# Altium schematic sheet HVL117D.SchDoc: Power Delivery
size 431 x 279 mm; Date: Not shown in title block; ApprovedBy: Not shown in title block; CheckedBy: Not shown in title block; Author: Not shown in title block; CompanyName: Not shown in title block; Engineer: Not shown in title block; Organization: Not shown in title block; Address1: Not shown in title block; Address2: Not shown in title block; Address3: Not shown in title block; Address4: Not shown in title block; DocumentNumber: 2; Revision: Use project parameter SCH_Rev; SheetNumber: 2; SheetTotal: 4; PageSetup: Record=PageOptions¦CenterHorizontal=True¦CenterVertical=True¦PrintScale=0.64¦XCorrection=1.00¦YCorrection=1.00¦PrintKind=0¦BorderSize=5000000¦LeftOffset=0¦BottomOffset=0¦Orientation=2¦PaperLength=1000¦PaperWidth=1000¦Scale=100¦PaperSource=15¦PrintQuality=600¦MediaType=1¦DitherType=10¦PaperKind=Letter¦PrintScaleMode=1
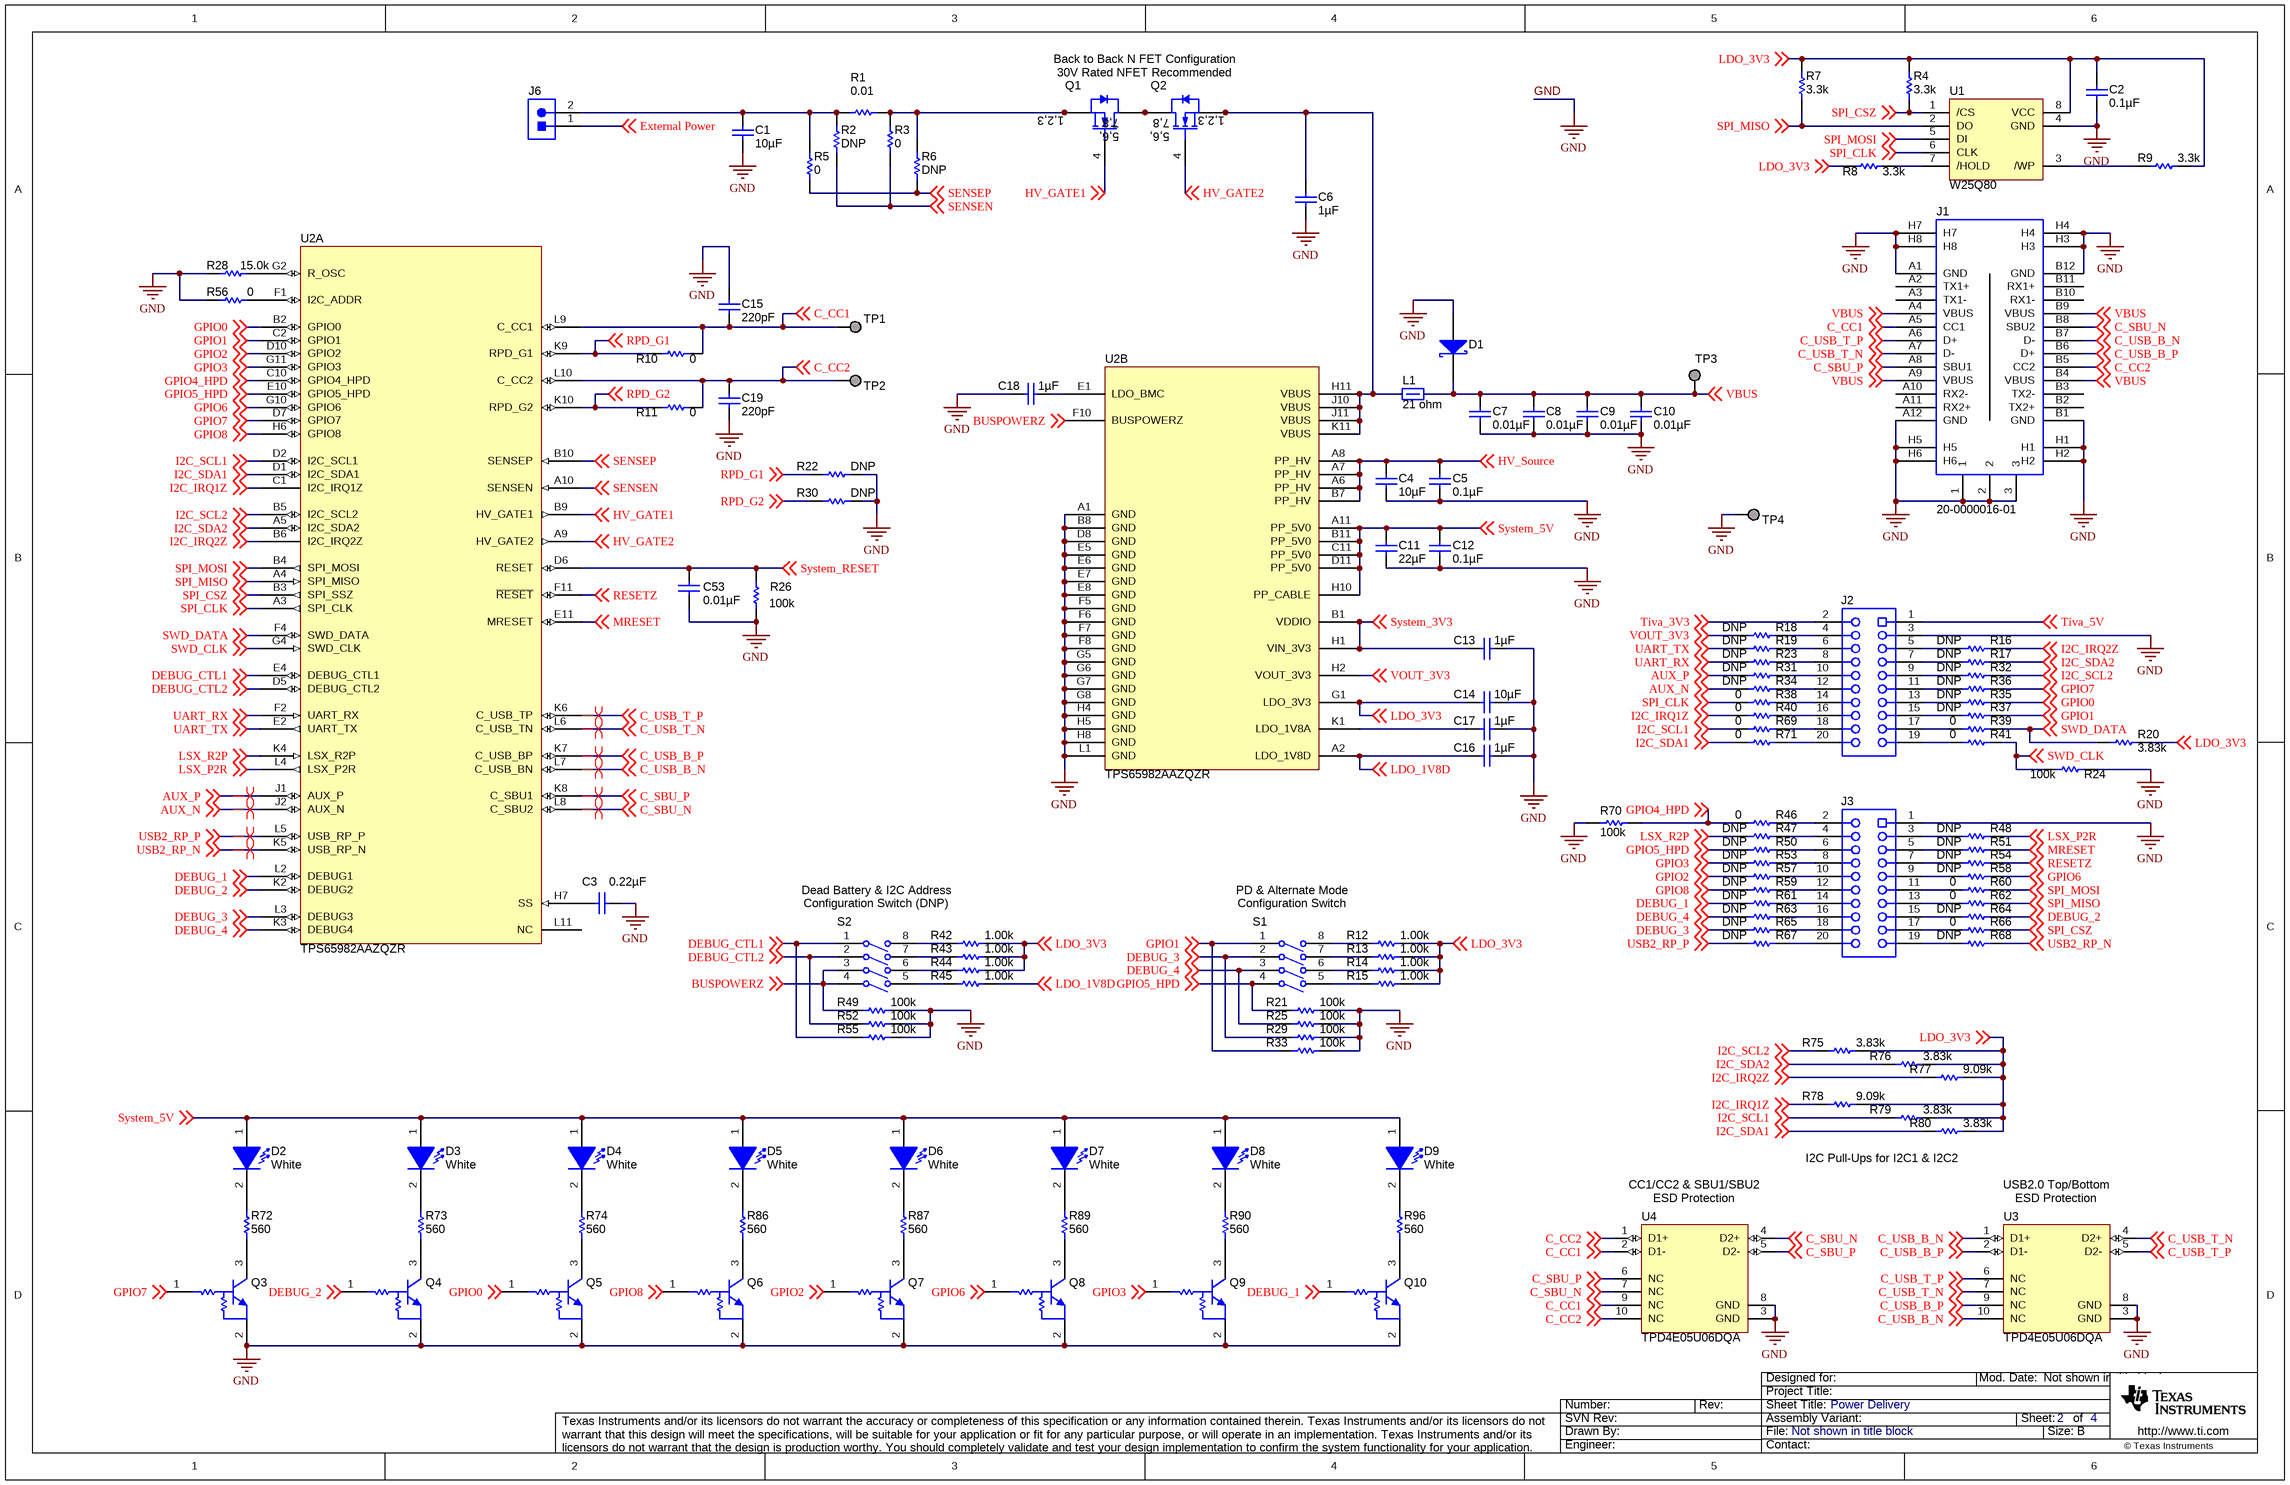
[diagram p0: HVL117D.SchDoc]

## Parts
C1  ValueDisplayed: 10µF  [0603]  (hidden comment: GRM188R61E106MA73)
C2  ValueDisplayed: 0.1µF  [0201]  (hidden comment: CL03A104KP3NNNC)
C3  ValueDisplayed: 0.22µF  [0201]  (hidden comment: GRM033R60J224ME90)
C4  ValueDisplayed: 10µF  [0603]  (hidden comment: GRM188R61E106MA73)
C5  ValueDisplayed: 0.1µF  [0402]  (hidden comment: C1005X7R1H104M)
C6  ValueDisplayed: 1µF  [0402]  (hidden comment: C1005JB1V105K050BC)
C7  ValueDisplayed: 0.01µF  [0402]  (hidden comment: GRM155R71H103KA88D)
C8  ValueDisplayed: 0.01µF  [0402]  (hidden comment: GRM155R71H103KA88D)
C9  ValueDisplayed: 0.01µF  [0402]  (hidden comment: GRM155R71H103KA88D)
C10  ValueDisplayed: 0.01µF  [0402]  (hidden comment: GRM155R71H103KA88D)
C11  ValueDisplayed: 22µF  [0603_100]  (hidden comment: GRM188R61A226ME15D)
C12  ValueDisplayed: 0.1µF  [0201]  (hidden comment: CL03A104KP3NNNC)
C13  ValueDisplayed: 1µF  [0201]  (hidden comment: CL03A105MP3NSNC)
C14  ValueDisplayed: 10µF  [0402]  (hidden comment: CL05A106MP5NUNC)
C15  ValueDisplayed: 220pF  [0201]  (hidden comment: GRM033R71E221KA01D)
C16  ValueDisplayed: 1µF  [0201]  (hidden comment: CL03A105MP3NSNC)
C17  ValueDisplayed: 1µF  [0201]  (hidden comment: CL03A105MP3NSNC)
C18  ValueDisplayed: 1µF  [0201]  (hidden comment: CL03A105MP3NSNC)
C19  ValueDisplayed: 220pF  [0201]  (hidden comment: GRM033R71E221KA01D)
C53  ValueDisplayed: 0.01µF  [0201]  (hidden comment: GRM033R61A103KA01D)
D1  B340A-13-F  [SMA]  (value not drawn)
D2  value White  [LW QH8G_White]  (hidden comment: LW QH8G-Q2S2-3K5L-1)
D3  value White  [LW QH8G_White]  (hidden comment: LW QH8G-Q2S2-3K5L-1)
D4  value White  [LW QH8G_White]  (hidden comment: LW QH8G-Q2S2-3K5L-1)
D5  value White  [LW QH8G_White]  (hidden comment: LW QH8G-Q2S2-3K5L-1)
D6  value White  [LW QH8G_White]  (hidden comment: LW QH8G-Q2S2-3K5L-1)
D7  value White  [LW QH8G_White]  (hidden comment: LW QH8G-Q2S2-3K5L-1)
D8  value White  [LW QH8G_White]  (hidden comment: LW QH8G-Q2S2-3K5L-1)
D9  value White  [LW QH8G_White]  (hidden comment: LW QH8G-Q2S2-3K5L-1)
J1  20-0000016-01  [Lintes_20-0000016-01]
J2  PPPC102LFBN-RC  [Sullins_PPPC102LFBN-RC]  (value not drawn)
J3  PPPC102LFBN-RC  [Sullins_PPPC102LFBN-RC]  (value not drawn)
J6  90120-0122  [CONN_90120-0122]  (value not drawn)
L1  value 21 ohm  [0805_HV]  (hidden comment: FBMJ2125HM210NT)
Q1  CSD17309Q3  [TRANS_NexFET_Q3]  (value not drawn)
Q2  CSD17309Q3  [TRANS_NexFET_Q3]  (value not drawn)
Q3  DTC114EUAT106  [SOT-323]  (value not drawn)
Q4  DTC114EUAT106  [SOT-323]  (value not drawn)
Q5  DTC114EUAT106  [SOT-323]  (value not drawn)
Q6  DTC114EUAT106  [SOT-323]  (value not drawn)
Q7  DTC114EUAT106  [SOT-323]  (value not drawn)
Q8  DTC114EUAT106  [SOT-323]  (value not drawn)
Q9  DTC114EUAT106  [SOT-323]  (value not drawn)
Q10  DTC114EUAT106  [SOT-323]  (value not drawn)
R1  value 0.01  [0805_HV]  (hidden comment: WSL0805R0100FEA18)
R2  ValueDisplayed: DNP  [0201M]  (hidden comment: ERJ-1GE0R00C)  (no BOM)
R3  ValueDisplayed: 0  [0201M]  (hidden comment: ERJ-1GE0R00C)
R4  ValueDisplayed: 3.3k  [0402]  (hidden comment: CRCW04023K30JNED)
R5  ValueDisplayed: 0  [0201M]  (hidden comment: ERJ-1GE0R00C)
R6  ValueDisplayed: DNP  [0201M]  (hidden comment: ERJ-1GE0R00C)
R7  ValueDisplayed: 3.3k  [0402]  (hidden comment: CRCW04023K30JNED)
R8  ValueDisplayed: 3.3k  [0402]  (hidden comment: CRCW04023K30JNED)
R9  ValueDisplayed: 3.3k  [0402]  (hidden comment: CRCW04023K30JNED)
R10  ValueDisplayed: 0  [0201M]  (hidden comment: ERJ-1GE0R00C)
R11  ValueDisplayed: 0  [0201M]  (hidden comment: ERJ-1GE0R00C)
R12  ValueDisplayed: 1.00k  [0201M]  (hidden comment: CRCW02011K00FKED)
R13  ValueDisplayed: 1.00k  [0201M]  (hidden comment: CRCW02011K00FKED)
R14  ValueDisplayed: 1.00k  [0201M]  (hidden comment: CRCW02011K00FKED)
R15  ValueDisplayed: 1.00k  [0201M]  (hidden comment: CRCW02011K00FKED)
R16  ValueDisplayed: DNP  [0201M]  (hidden comment: ERJ-1GE0R00C)
R17  ValueDisplayed: DNP  [0201M]  (hidden comment: ERJ-1GE0R00C)
R18  ValueDisplayed: DNP  [0201M]  (hidden comment: ERJ-1GE0R00C)
R19  ValueDisplayed: DNP  [0201M]  (hidden comment: ERJ-1GE0R00C)
R20  ValueDisplayed: 3.83k  [0201M]  (hidden comment: CRCW02013K83FKED)
R21  ValueDisplayed: 100k  [0201M]  (hidden comment: CRCW0201100KFKED)
R22  ValueDisplayed: DNP  [0201M]  (hidden comment: ERJ-1GE0R00C)
R23  ValueDisplayed: DNP  [0201M]  (hidden comment: ERJ-1GE0R00C)
R24  ValueDisplayed: 100k  [0201M]  (hidden comment: CRCW0201100KFKED)
R25  ValueDisplayed: 100k  [0201M]  (hidden comment: CRCW0201100KFKED)
R26  ValueDisplayed: 100k  [0201M]  (hidden comment: CRCW0201100KFKED)
R28  ValueDisplayed: 15.0k  [0402]  (hidden comment: CRCW040215K0FKED)
R29  ValueDisplayed: 100k  [0201M]  (hidden comment: CRCW0201100KFKED)
R30  ValueDisplayed: DNP  [0201M]  (hidden comment: ERJ-1GE0R00C)
R31  ValueDisplayed: DNP  [0201M]  (hidden comment: ERJ-1GE0R00C)
R32  ValueDisplayed: DNP  [0201M]  (hidden comment: ERJ-1GE0R00C)
R33  ValueDisplayed: 100k  [0201M]  (hidden comment: CRCW0201100KFKED)
R34  ValueDisplayed: DNP  [0201M]  (hidden comment: ERJ-1GE0R00C)
R35  ValueDisplayed: DNP  [0201M]  (hidden comment: ERJ-1GE0R00C)
R36  ValueDisplayed: DNP  [0201M]  (hidden comment: ERJ-1GE0R00C)
R37  ValueDisplayed: DNP  [0201M]  (hidden comment: ERJ-1GE0R00C)
R38  ValueDisplayed: 0  [0201M]  (hidden comment: ERJ-1GE0R00C)
R39  ValueDisplayed: 0  [0201M]  (hidden comment: ERJ-1GE0R00C)
R40  ValueDisplayed: 0  [0201M]  (hidden comment: ERJ-1GE0R00C)
R41  ValueDisplayed: 0  [0201M]  (hidden comment: ERJ-1GE0R00C)
R42  ValueDisplayed: 1.00k  [0201M]  (hidden comment: CRCW02011K00FKED)
R43  ValueDisplayed: 1.00k  [0201M]  (hidden comment: CRCW02011K00FKED)
R44  ValueDisplayed: 1.00k  [0201M]  (hidden comment: CRCW02011K00FKED)
R45  ValueDisplayed: 1.00k  [0201M]  (hidden comment: CRCW02011K00FKED)
R46  ValueDisplayed: 0  [0201M]  (hidden comment: ERJ-1GE0R00C)
R47  ValueDisplayed: DNP  [0201M]  (hidden comment: ERJ-1GE0R00C)
R48  ValueDisplayed: DNP  [0201M]  (hidden comment: ERJ-1GE0R00C)
R49  ValueDisplayed: 100k  [0201M]  (hidden comment: CRCW0201100KFKED)
R50  ValueDisplayed: DNP  [0201M]  (hidden comment: ERJ-1GE0R00C)
R51  ValueDisplayed: DNP  [0201M]  (hidden comment: ERJ-1GE0R00C)
R52  ValueDisplayed: 100k  [0201M]  (hidden comment: CRCW0201100KFKED)
R53  ValueDisplayed: DNP  [0201M]  (hidden comment: ERJ-1GE0R00C)
R54  ValueDisplayed: DNP  [0201M]  (hidden comment: ERJ-1GE0R00C)
R55  ValueDisplayed: 100k  [0201M]  (hidden comment: CRCW0201100KFKED)
R56  ValueDisplayed: 0  [0201M]  (hidden comment: ERJ-1GE0R00C)
R57  ValueDisplayed: DNP  [0201M]  (hidden comment: ERJ-1GE0R00C)
R58  ValueDisplayed: DNP  [0201M]  (hidden comment: ERJ-1GE0R00C)
R59  ValueDisplayed: DNP  [0201M]  (hidden comment: ERJ-1GE0R00C)
R60  ValueDisplayed: 0  [0201M]  (hidden comment: ERJ-1GE0R00C)
R61  ValueDisplayed: DNP  [0201M]  (hidden comment: ERJ-1GE0R00C)
R62  ValueDisplayed: 0  [0201M]  (hidden comment: ERJ-1GE0R00C)
R63  ValueDisplayed: DNP  [0201M]  (hidden comment: ERJ-1GE0R00C)
R64  ValueDisplayed: DNP  [0201M]  (hidden comment: ERJ-1GE0R00C)
R65  ValueDisplayed: DNP  [0201M]  (hidden comment: ERJ-1GE0R00C)
R66  ValueDisplayed: 0  [0201M]  (hidden comment: ERJ-1GE0R00C)
R67  ValueDisplayed: DNP  [0201M]  (hidden comment: ERJ-1GE0R00C)
R68  ValueDisplayed: DNP  [0201M]  (hidden comment: ERJ-1GE0R00C)
R69  ValueDisplayed: 0  [0201M]  (hidden comment: ERJ-1GE0R00C)
R70  ValueDisplayed: 100k  [0201M]  (hidden comment: CRCW0201100KFKED)
R71  ValueDisplayed: 0  [0201M]  (hidden comment: ERJ-1GE0R00C)
R72  ValueDisplayed: 560  [0402]  (hidden comment: CRCW0402560RJNED)
R73  ValueDisplayed: 560  [0402]  (hidden comment: CRCW0402560RJNED)
R74  ValueDisplayed: 560  [0402]  (hidden comment: CRCW0402560RJNED)
R75  ValueDisplayed: 3.83k  [0201M]  (hidden comment: CRCW02013K83FKED)
R76  ValueDisplayed: 3.83k  [0201M]  (hidden comment: CRCW02013K83FKED)
R77  ValueDisplayed: 9.09k  [0201M]  (hidden comment: CRCW02019K09FKED)
R78  ValueDisplayed: 9.09k  [0201M]  (hidden comment: CRCW02019K09FKED)
R79  ValueDisplayed: 3.83k  [0201M]  (hidden comment: CRCW02013K83FKED)
R80  ValueDisplayed: 3.83k  [0201M]  (hidden comment: CRCW02013K83FKED)
R86  ValueDisplayed: 560  [0402]  (hidden comment: CRCW0402560RJNED)
R87  ValueDisplayed: 560  [0402]  (hidden comment: CRCW0402560RJNED)
R89  ValueDisplayed: 560  [0402]  (hidden comment: CRCW0402560RJNED)
R90  ValueDisplayed: 560  [0402]  (hidden comment: CRCW0402560RJNED)
R96  ValueDisplayed: 560  [0402]  (hidden comment: CRCW0402560RJNED)
S1  TDA04H0SB1  [SW_TDA04H0SB1]  (value not drawn)
S2  TDA04H0SB1  [SW_TDA04H0SB1]  (value not drawn)
TP1  TESTPOINT  [Keystone_5019]  (value not drawn)
TP2  TESTPOINT  [Keystone_5019]  (value not drawn)
TP3  TESTPOINT  [Keystone_5019]  (value not drawn)
TP4  TESTPOINT  [Keystone_5019]  (value not drawn)
U1  W25Q80  [SOIC127P600-8N-W25Q40CL]
U2  TPS65982AAZQZR  [ZQZ0096A_Oval]  (parts A,B of 2)
U3  TPD4E05U06DQA  [DQA0010A]
U4  TPD4E05U06DQA  [DQA0010A]

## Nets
GND: C1.2 C2.2 C3.2 C4.2 C5.2 C6.2 C7.2 C8.2 C9.2 C10.2 C11.2 C12.2 C13.2 C14.2 C15.2 C16.2 C17.2 C18.2 C19.2 C53.2 D1.2(A) J1.1 J1.2 J1.3 J1.A1(GND) J1.A12(GND) J1.B1(GND) J1.B12(GND) J1.H1 J1.H2 J1.H3 J1.H4 J1.H5 J1.H6 J1.H7 J1.H8 J2.3 J3.1 Q3.2(E) Q4.2(E) Q5.2(E) Q6.2(E) Q7.2(E) Q8.2(E) Q9.2(E) Q10.2(E) R21.2 R22.2 R24.2 R25.2 R26.1 R28.1 R29.2 R30.2 R33.2 R49.2 R52.2 R55.2 R56.1 R70.1 TP4.1 U1.4(GND) U2.A1(GND) U2.B8(GND) U2.D8(GND) U2.E5(GND) U2.E6(GND) U2.E7(GND) U2.E8(GND) U2.F5(GND) U2.F6(GND) U2.F7(GND) U2.F8(GND) U2.G5(GND) U2.G6(GND) U2.G7(GND) U2.G8(GND) U2.H4(GND) U2.H5(GND) U2.H8(GND) U2.L1(GND) U3.3(GND) U3.8(GND) U4.3(GND) U4.8(GND)
AUX_N: R34.2 U2.J2(AUX_N) ; off-sheet AUX_N
AUX_P: R31.2 U2.J1(AUX_P) ; off-sheet AUX_P
BUSPOWERZ: R49.1 S2.3(A3) S2.4(A4) U2.F10(BUSPOWERZ) ; off-sheet BUSPOWERZ
C_CC1: C15.1 J1.A5(CC1) R10.2 TP1.1 U2.L9(C_CC1) U4.2(D1-) U4.9(NC) ; off-sheet C_CC1
C_CC2: C19.1 J1.B5(CC2) R11.2 TP2.1 U2.L10(C_CC2) U4.1(D1+) U4.10(NC) ; off-sheet C_CC2
C_SBU_N: J1.B8(SBU2) U2.L8(C_SBU2) U4.4(D2+) U4.7(NC) ; off-sheet C_SBU_N
C_SBU_P: J1.A8(SBU1) U2.K8(C_SBU1) U4.5(D2-) U4.6(NC) ; off-sheet C_SBU_P
C_USB_B_N: J1.B7(D-) U2.L7(C_USB_BN) U3.1(D1+) U3.10(NC) ; off-sheet C_USB_B_N
C_USB_B_P: J1.B6(D+) U2.K7(C_USB_BP) U3.2(D1-) U3.9(NC) ; off-sheet C_USB_B_P
C_USB_T_N: J1.A7(D-) U2.L6(C_USB_TN) U3.4(D2+) U3.7(NC) ; off-sheet C_USB_T_N
C_USB_T_P: J1.A6(D+) U2.K6(C_USB_TP) U3.5(D2-) U3.6(NC) ; off-sheet C_USB_T_P
DEBUG_1: Q10.1(B) R61.1 U2.L2(DEBUG1) ; off-sheet DEBUG_1
DEBUG_2: Q4.1(B) R64.1 U2.K2(DEBUG2) ; off-sheet DEBUG_2
DEBUG_3: R29.1 R65.1 S1.2(A2) U2.L3(DEBUG3) ; off-sheet DEBUG_3
DEBUG_4: R25.1 R63.1 S1.3(A3) U2.K3(DEBUG4) ; off-sheet DEBUG_4
DEBUG_CTL1: R55.1 S2.1(A1) U2.E4(DEBUG_CTL1) ; off-sheet DEBUG_CTL1
DEBUG_CTL2: R52.1 S2.2(A2) U2.D5(DEBUG_CTL2) ; off-sheet DEBUG_CTL2
External Power: J6.1 ; off-sheet External Power
GPIO0: Q5.1(B) R35.1 U2.B2(GPIO0) ; off-sheet GPIO0
GPIO1: R33.1 R37.1 S1.1(A1) U2.C2(GPIO1) ; off-sheet GPIO1
GPIO2: Q7.1(B) R57.1 U2.D10(GPIO2) ; off-sheet GPIO2
GPIO3: Q9.1(B) R53.1 U2.G11(GPIO3) ; off-sheet GPIO3
GPIO4_HPD: R46.2 R70.2 U2.C10(GPIO4_HPD) ; off-sheet GPIO4_HPD
GPIO5_HPD: R21.1 R50.2 S1.4(A4) U2.E10(GPIO5_HPD) ; off-sheet GPIO5_HPD
GPIO6: Q8.1(B) R58.1 U2.G10(GPIO6) ; off-sheet GPIO6
GPIO7: Q3.1(B) R36.1 U2.D7(GPIO7) ; off-sheet GPIO7
GPIO8: Q6.1(B) R59.1 U2.H6(GPIO8) ; off-sheet GPIO8
HV_GATE1: Q1.4(G) U2.B9(HV_GATE1) ; off-sheet HV_GATE1
HV_GATE2: Q2.4(G) U2.A9(HV_GATE2) ; off-sheet HV_GATE2
HV_Source: C4.1 C5.1 U2.A6(PP_HV) U2.A7(PP_HV) U2.A8(PP_HV) U2.B7(PP_HV) ; off-sheet HV_Source
I2C_IRQ1Z: R40.2 R78.1 U2.C1(I2C_IRQ1Z) ; off-sheet I2C_IRQ1Z
I2C_IRQ2Z: R16.1 R77.1 U2.B6(I2C_IRQ2Z) ; off-sheet I2C_IRQ2Z
I2C_SCL1: R69.2 R79.1 U2.D2(I2C_SCL1) ; off-sheet I2C_SCL1
I2C_SCL2: R32.1 R75.1 U2.B5(I2C_SCL2) ; off-sheet I2C_SCL2
I2C_SDA1: R71.2 R80.1 U2.D1(I2C_SDA1) ; off-sheet I2C_SDA1
I2C_SDA2: R17.1 R76.1 U2.A5(I2C_SDA2) ; off-sheet I2C_SDA2
LDO_1V8D: C16.1 R45.2 U2.A2(LDO_1V8D) ; off-sheet LDO_1V8D
LDO_3V3: C2.1 C14.1 R4.1 R7.1 R8.1 R9.2 R12.2 R13.2 R14.2 R15.2 R20.2 R42.2 R43.2 R44.2 R75.2 R76.2 R77.2 R78.2 R79.2 R80.2 U1.8(VCC) U2.G1(LDO_3V3) ; off-sheet LDO_3V3
LSX_P2R: R48.2 U2.L4(LSX_P2R) ; off-sheet LSX_P2R
LSX_R2P: R47.2 U2.K4(LSX_R2P) ; off-sheet LSX_R2P
MRESET: R51.1 U2.E11(MRESET) ; off-sheet MRESET
RESETZ: R54.1 U2.F11(~{RESET}) ; off-sheet RESETZ
RPD_G1: R10.1 R22.1 U2.K9(RPD_G1) ; off-sheet RPD_G1
RPD_G2: R11.1 R30.1 U2.K10(RPD_G2) ; off-sheet RPD_G2
SENSEN: R2.1 R3.1 U2.A10(SENSEN) ; off-sheet SENSEN
SENSEP: R5.1 R6.1 U2.B10(SENSEP) ; off-sheet SENSEP
SPI_CLK: R38.2 U1.6(CLK) U2.A3(SPI_CLK) ; off-sheet SPI_CLK
SPI_CSZ: R4.2 R66.2 U1.1(/CS) U2.B3(SPI_SSZ) ; off-sheet SPI_CSZ
SPI_MISO: R7.2 R62.1 U1.2(DO) U2.A4(SPI_MISO) ; off-sheet SPI_MISO
SPI_MOSI: R60.1 U1.5(DI) U2.B4(SPI_MOSI) ; off-sheet SPI_MOSI
SWD_CLK: R24.1 R41.1 U2.G4(SWD_CLK) ; off-sheet SWD_CLK
SWD_DATA: R20.1 R39.1 U2.F4(SWD_DATA) ; off-sheet SWD_DATA
System_3V3: C13.1 U2.B1(VDDIO) U2.H1(VIN_3V3) ; off-sheet System_3V3
System_5V: C11.1 C12.1 D2.1(A) D3.1(A) D4.1(A) D5.1(A) D6.1(A) D7.1(A) D8.1(A) D9.1(A) U2.A11(PP_5V0) U2.B11(PP_5V0) U2.C11(PP_5V0) U2.D11(PP_5V0) U2.H10(PP_CABLE) ; off-sheet System_5V
System_RESET: C53.1 R26.2 U2.D6(RESET) ; off-sheet System_RESET
Tiva_3V3: J2.2 ; off-sheet Tiva_3V3
Tiva_5V: J2.1 ; off-sheet Tiva_5V
UART_RX: R23.2 U2.F2(UART_RX) ; off-sheet UART_RX
UART_TX: R19.1 U2.E2(UART_TX) ; off-sheet UART_TX
USB2_RP_N: R68.2 U2.K5(USB_RP_N) ; off-sheet USB2_RP_N
USB2_RP_P: R67.2 U2.L5(USB_RP_P) ; off-sheet USB2_RP_P
VBUS: C7.1 C8.1 C9.1 C10.1 D1.1(K) J1.A4(VBUS) J1.A9(VBUS) J1.B4(VBUS) J1.B9(VBUS) L1.2 TP3.1 ; off-sheet VBUS
VOUT_3V3: R18.1 U2.H2(VOUT_3V3) ; off-sheet VOUT_3V3
NetC1_1: C1.1 J6.2 R1.1 R2.2 R5.2
NetC3_1: C3.1 U2.H7(SS)
NetC6_1: C6.1 L1.1 Q2.1(S) Q2.2(S) Q2.3(S) U2.H11(VBUS) U2.J10(VBUS) U2.J11(VBUS) U2.K11(VBUS)
NetC17_1: C17.1 U2.K1(LDO_1V8A)
NetC18_1: C18.1 U2.E1(LDO_BMC)
NetD2_2: D2.2(K) R72.2
NetD3_2: D3.2(K) R73.2
NetD4_2: D4.2(K) R74.2
NetD5_2: D5.2(K) R86.2
NetD6_2: D6.2(K) R87.2
NetD7_2: D7.2(K) R89.2
NetD8_2: D8.2(K) R90.2
NetD9_2: D9.2(K) R96.2
NetJ2_4: J2.4 R18.2
NetJ2_5: J2.5 R16.2
NetJ2_6: J2.6 R19.2
NetJ2_7: J2.7 R17.2
NetJ2_8: J2.8 R23.1
NetJ2_9: J2.9 R32.2
NetJ2_10: J2.10 R31.1
NetJ2_11: J2.11 R36.2
NetJ2_12: J2.12 R34.1
NetJ2_13: J2.13 R35.2
NetJ2_14: J2.14 R38.1
NetJ2_15: J2.15 R37.2
NetJ2_16: J2.16 R40.1
NetJ2_17: J2.17 R39.2
NetJ2_18: J2.18 R69.1
NetJ2_19: J2.19 R41.2
NetJ2_20: J2.20 R71.1
NetJ3_2: J3.2 R46.1
NetJ3_3: J3.3 R48.1
NetJ3_4: J3.4 R47.1
NetJ3_5: J3.5 R51.2
NetJ3_6: J3.6 R50.1
NetJ3_7: J3.7 R54.2
NetJ3_8: J3.8 R53.2
NetJ3_9: J3.9 R58.2
NetJ3_10: J3.10 R57.2
NetJ3_11: J3.11 R60.2
NetJ3_12: J3.12 R59.2
NetJ3_13: J3.13 R62.2
NetJ3_14: J3.14 R61.2
NetJ3_15: J3.15 R64.2
NetJ3_16: J3.16 R63.2
NetJ3_17: J3.17 R66.1
NetJ3_18: J3.18 R65.2
NetJ3_19: J3.19 R68.1
NetJ3_20: J3.20 R67.1
NetQ1_1: Q1.1(S) Q1.2(S) Q1.3(S) R1.2 R3.2 R6.2
NetQ1_5: Q1.5(D) Q1.6(D) Q1.7(D) Q1.8(D) Q2.5(D) Q2.6(D) Q2.7(D) Q2.8(D)
NetQ3_3: Q3.3(C) R72.1
NetQ4_3: Q4.3(C) R73.1
NetQ5_3: Q5.3(C) R74.1
NetQ6_3: Q6.3(C) R86.1
NetQ7_3: Q7.3(C) R87.1
NetQ8_3: Q8.3(C) R89.1
NetQ9_3: Q9.3(C) R90.1
NetQ10_3: Q10.3(C) R96.1
NetR8_2: R8.2 U1.7(/HOLD)
NetR9_1: R9.1 U1.3(/WP)
NetR12_1: R12.1 S1.8(B1)
NetR13_1: R13.1 S1.7(B2)
NetR14_1: R14.1 S1.6(B3)
NetR15_1: R15.1 S1.5(B4)
NetR28_2: R28.2 U2.G2(R_OSC)
NetR42_1: R42.1 S2.8(B1)
NetR43_1: R43.1 S2.7(B2)
NetR44_1: R44.1 S2.6(B3)
NetR45_1: R45.1 S2.5(B4)
NetR56_2: R56.2 U2.F1(I2C_ADDR)

Not connected (* = marked no-connect by the designer): J1 A2(TX1+) A3(TX1-) A10(RX2-) A11(RX2+) B2(TX2+) B3(TX2-) B10(RX1-) B11(RX1+); U2 L11(NC)

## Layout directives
differential pair: AUX_N, AUX_P, C_SBU_N, C_SBU_P, C_USB_B_N, C_USB_B_P, C_USB_T_N, C_USB_T_P, USB2_RP_N, USB2_RP_P

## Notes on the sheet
- Back to Back N FET Configuration
- 30V Rated NFET Recommended
- Dead Battery & I2C Address
- Configuration Switch (DNP)
- PD & Alternate Mode
- Configuration Switch
- I2C Pull-Ups for I2C1 & I2C2
- (near U4) CC1/CC2 & SBU1/SBU2
- (near U4) ESD Protection
- USB2.0 Top/Bottom
- (near U3) ESD Protection

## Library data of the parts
C1 C4 = GRM188R61E106MA73: CAP, CERM, 10 µF, 25 V, +/- 20%, X5R, 0603; Manufacturer: MuRata; Polarized: N; CompType: Capacitor; Value: 10uF; U/M: EA; Cap_F: 0.00001; Tolerance_%: 20; Value1: Unknown; VDC_V: 25; Value2: 25V; TaMin_C: -55; TaMax_C: 85
C2 C12 = CL03A104KP3NNNC: CAP, CERM, 0.1 µF, 10 V, +/- 10%, X5R, 0201; Manufacturer: Samsung; Polarized: N; CompType: Capacitor; Value: 0.1uF; U/M: EA; Cap_F: 0.0000001; Tolerance_%: 10; Value1: Unknown; Value2: 10V; TaMin_C: -55; TaMax_C: 85
C3 = GRM033R60J224ME90: CAP, CERM, 0.22 µF, 6.3 V, +/- 20%, X5R, 0201; Manufacturer: MuRata; Polarized: N; CompType: Capacitor; Value: 0.22uF; U/M: EA; Cap_F: 0.00000022; Tolerance_%: 20; Value1: Unknown; VDC_V: 6.3; Value2: 6.3V; TaMin_C: -55; TaMax_C: 85
C5 = C1005X7R1H104M: CAP, CERM, 0.1 µF, 50 V, +/- 20%, C0G/NP0, 0402; Manufacturer: TDK; Polarized: N; CompType: Capacitor; Value: 0.1uF; U/M: EA; Cap_F: 0.0000001; Tolerance_%: 20; Value1: Unknown; VDC_V: 50; Value2: 50V; TaMin_C: -55; TaMax_C: 125
C6 = C1005JB1V105K050BC: CAP, CERM, 1 µF, 35 V, +/- 10%, JB, 0402; Manufacturer: TDK; Polarized: N; CompType: Capacitor; Value: 1uF; U/M: EA; Cap_F: 0.000001; Tolerance_%: 10; Value1: Unknown; VDC_V: 35; Value2: 35V; TaMin_C: -25; TaMax_C: 85
C7-C10 = GRM155R71H103KA88D: CAP, CERM, 0.01 µF, 50 V, +/- 10%, X7R, 0402; Manufacturer: MuRata; Polarized: N; CompType: Capacitor; Value: 0.01uF; U/M: EA; Cap_F: 0.00000001; Tolerance_%: 10; Value1: Unknown; VDC_V: 50; Value2: 50V; TaMin_C: -55; TaMax_C: 125
C11 = GRM188R61A226ME15D: CAP, CERM, 22 µF, 10 V, +/- 20%, X5R, 0603; Manufacturer: MuRata; Polarized: N; CompType: Capacitor; Value: 22uF; U/M: EA; Cap_F: 0.000022; Tolerance_%: 20; Value1: Unknown; VDC_V: 10; Value2: 10V; TaMin_C: -55; TaMax_C: 85; Cap_Case: 0603
C13 C16-C18 = CL03A105MP3NSNC: CAP, CERM, 1 µF, 10 V, +/- 20%, X5R, 0201; Manufacturer: Samsung; Polarized: N; CompType: Capacitor; Value: 1uF; U/M: EA; Cap_F: 0.000001; Tolerance_%: 20; Value1: Unknown; VDC_V: 10; Value2: 10V; TaMin_C: -55; TaMax_C: 85
C14 = CL05A106MP5NUNC: CAP, CERM, 10 µF, 10 V, +/- 20%, X5R, 0402; Manufacturer: Samsung; Polarized: N; CompType: Capacitor; Value: 10uF; U/M: EA; Cap_F: 0.00001; Tolerance_%: 20; Value1: Unknown; VDC_V: 10; Value2: 10V; TaMin_C: -55; TaMax_C: 85
C15 C19 = GRM033R71E221KA01D: CAP, CERM, 220 pF, 25 V, +/- 10%, X7R, 0201; Manufacturer: MuRata; Polarized: N; CompType: Capacitor; Value: 220pF; U/M: EA; Cap_F: 0.00000000022; Tolerance_%: 10; Value1: Unknown; VDC_V: 25; Value2: 25V; TaMin_C: -55; TaMax_C: 125
C53 = GRM033R61A103KA01D: CAP, CERM, 0.01 µF, 10 V, +/- 10%, X5R, 0201; Manufacturer: MuRata; Polarized: N; CompType: Capacitor; Value: 0.01uF; U/M: EA; Cap_F: 0.00000001; Tolerance_%: 10; Value1: Unknown; Value2: 10V; TaMin_C: -55; TaMax_C: 85
D1 = B340A-13-F: Diode, Schottky, 40 V, 3 A, SMA; Manufacturer: Diodes Inc.; U/M: EA; Vf_V: 0.5; Value: 40V; Value1: 3A; Value2: 0.5V; Io_A: 3; Vr_V: 40; TJmax_C: 125; RJC_CperW: 25
D2-D9 = LW QH8G-Q2S2-3K5L-1: LED, White, SMD; Manufacturer: OSRAM; Vf_V: 2.8; Value2: 2.8V; Io_A: 0.005; Vr_V: 5; Ir_A: 1e-008; Tjmax_C: 95; Value1: W; Angle: 120; U/M: EA
J1 = 20-0000016-01: Connector, Receptacle, USB Type C, R/A, SMT; Manufacturer: Lintes Technology; SymbolCreator: Altium; U/M: EA
J2 J3 = PPPC102LFBN-RC: Receptacle, 100mil, 10x2, Gold, TH; Manufacturer: Sullins Connector Solutions; SymbolCreator: a0412235; U/M: EA
J6 = 90120-0122: Header, 100mil, 2x1, Tin, TH; Manufacturer: Molex; SymbolCreator: a0412235; U/M: EA
L1 = FBMJ2125HM210NT: Ferrite Bead, 21 ohm @ 100MHz, 6A, 0805; Manufacturer: Taiyo Yuden; Imax_A: 6; DCR_ohm: 0.004; Value1: 0.004 ohm; ZTyp@100MHz_Ohm: 21
Q1 Q2 = CSD17309Q3: MOSFET, N-CH, 30 V, 60 A, SON 3.3x3.3mm; Manufacturer: Texas Instruments; Alternate Manufacturer: None; U/M: EA; ChType: N; Value: 30V; VdsMax_V: 30; Value1: 0.0049 ohm; Rdson45_ohm: 0.0049; Value2: 7.5 nC; QgTyp_nC: 7.5; Vgs_V: 10; IdsMax_A: 60
Q3-Q10 = DTC114EUAT106, Rohm: Transistor, NPN, 50 V, 0.05 A, SOT-323; Manufacturer: Rohm; SymbolCreator: a0411947; PNP: 0; NPN: 1; Vceo_V: 50; Vcesat1_V: 0.3; Value: 50 V; IcRated_A: 0.05; Value1: 0.05 A; TaMin_C: -55; TaMax_C: 150; CompType: BJT; U/M: EA
R1 = WSL0805R0100FEA18: RES, 0.01 ohm, 1%, 0.25W, 0805; Manufacturer: Vishay-Dale; CompType: Resistor; Value_Code: R010; Tolerance_%: 1; Power_W: 0.25; TempCo: 75 ppm/C; EIA_Code: E96; U/M: EA
R2 R3 R5 R6 R10 R11 R16-R19 R22 R23 R30-R32 R34-R41 R46-R48 R50 R51 R53 R54 R56-R69 R71 = ERJ-1GE0R00C: RES, 0, 5%, 0.05 W, 0201; Manufacturer: Panasonic; CompType: Resistor; Value: 0; Value_Code: 0000; Tolerance_%: 5; Power_W: 0.05; Value2: 0.05W; VDC_V: 15; TempCo: 600 ppm/C; EIA_Code: E24; U/M: EA
R4 R7-R9 = CRCW04023K30JNED: RES, 3.3 k, 5%, 0.063 W, 0402; Manufacturer: Vishay-Dale; CompType: Resistor; Value: 3.3k; Res_ohm: 3300; Value_Code: 3k30; Tolerance_%: 5; Power_W: 0.063; Value2: 0.063W; VDC_V: 50; TempCo: 200 ppm/C; EIA_Code: E24; U/M: EA
R12-R15 R42-R45 = CRCW02011K00FKED: RES, 1.00 k, 1%, 0.05 W, 0201; Manufacturer: Vishay-Dale; CompType: Resistor; Value: 1.00k; Res_ohm: 1000; Value_Code: 1k00; Tolerance_%: 1; Power_W: 0.05; Value2: 0.05W; VDC_V: 30; TempCo: 100 ppm/C; EIA_Code: E96; U/M: EA
R20 R75 R76 R79 R80 = CRCW02013K83FKED: RES, 3.83 k, 1%, 0.05 W, 0201; Manufacturer: Vishay-Dale; CompType: Resistor; Value: 3.83k; Res_ohm: 3830; Value_Code: 3k83; Tolerance_%: 1; Power_W: 0.05; Value2: 0.05W; VDC_V: 30; TempCo: 100 ppm/C; EIA_Code: E96; U/M: EA
R21 R24-R26 R29 R33 R49 R52 R55 R70 = CRCW0201100KFKED: RES, 100 k, 1%, 0.05 W, 0201; Manufacturer: Vishay-Dale; CompType: Resistor; Value: 100k; Res_ohm: 100000; Tolerance_%: 1; Power_W: 0.05; Value2: 0.05W; VDC_V: 30; TempCo: 100 ppm/C; EIA_Code: E96; U/M: EA
R28 = CRCW040215K0FKED: RES, 15.0 k, 1%, 0.063 W, 0402; Manufacturer: Vishay-Dale; CompType: Resistor; Value: 15.0k; Res_ohm: 15000; Value_Code: 15k0; Tolerance_%: 1; Power_W: 0.063; Value2: 0.063W; VDC_V: 50; TempCo: 100 ppm/C; EIA_Code: E96; U/M: EA
R72-R74 R86 R87 R89 R90 R96 = CRCW0402560RJNED: RES, 560, 5%, 0.063 W, 0402; Manufacturer: Vishay-Dale; CompType: Resistor; Value: 560; Value_Code: 560R; Tolerance_%: 5; Power_W: 0.063; Value2: 0.063W; VDC_V: 50; TempCo: 200 ppm/C; EIA_Code: E24; U/M: EA
R77 R78 = CRCW02019K09FKED: RES, 9.09 k, 1%, 0.05 W, 0201; Manufacturer: Vishay-Dale; CompType: Resistor; Value: 9.09k; Res_ohm: 9090; Value_Code: 9k09; Tolerance_%: 1; Power_W: 0.05; Value2: 0.05W; VDC_V: 30; TempCo: 100 ppm/C; EIA_Code: E96; U/M: EA
S1 S2 = TDA04H0SB1: DIP Switch, SPST 4Pos, Slide, SMT; Manufacturer: C&K Components; SymbolCreator: a0412235; VDC_V: 24; SwitchFunction: Off-On; PositionCount: 4; CurrentRating_mA: 20
TP1-TP4 = 5019: Test Point, Miniature, SMT; Manufacturer: Keystone; CompType: Test Point Loop; U/M: EA
U1 = W25Q40CL: Manufacturer: Used in BOM report; SymbolVersion: use current date i.e. 2008-05-20; SymbolCreator: Use a-id; CompType: Used in some BOM reports.  Useful for finding later.; U/M: EA, IN, or GM
U2 = TPS65982AAZQZR: TPS65982 Preview Specification, ZQZ0096A; Manufacturer: Texas Instruments; SymbolCreator: Altium; CompType: IC; U/M: EA
U3 U4 = TPD4E05U06DQA: 1, 4, 6 CHANNEL PROTECTION SOLUTION FOR SUPER-SPEED (UP TO 6 GBPS) INTERFACE, DQA0010A; Alternate Manufacturer: None; Manufacturer: Texas Instruments; SymbolCreator: a0411947; CompType: IC; U/M: EA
